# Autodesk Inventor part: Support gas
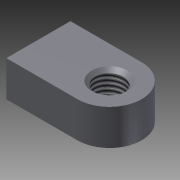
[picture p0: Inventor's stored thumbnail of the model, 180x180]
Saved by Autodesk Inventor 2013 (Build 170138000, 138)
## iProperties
Shininess: 64.0
Length Units: 11269
Angle Units: 11279
Time Units: 11290
Mass Units: 11283
Length Display Precision: 3
Angle Display Precision: 2
Compacted: True
Part Number: Support gas
Document SubType Name: Modeling
Created: 2005-02
Material: Steel, Mild
Designer: =<Author>
Manufacturer: Standard
Standards Organization: Custom
Description: Support
Density: 7.86 g/cm^3
Mass: 34.1318 g
Surface Area: 19.6117 cm^2
Volume: 4.34247 cm^3
Density: 0.0
Volumn: 0.0
Area: 0.0
PropertySet Name: Model Information
Control State: 0
Master: False
Checked Out: False
Checked Out Date: 2008-10-15
Last Check In Date: 2008-10-15
Author: PVitaliy
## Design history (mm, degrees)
sketch "Эскиз1"
  geometry: L1 (0.047, 0)-(20.047, 0); L2 (20.047, 18)-(0.047, 18); L3 (0.047, 18)-(0.047, 0); C1 r 4 at (20.047, 9); A1 r 9 centre (20.047, 9) between (20.047, 0) and (20.047, 18)
  constraints: 6 end point, 2 centre point, 2 point on circle, 2 tangent, 1 coincident, 1 horizontal, 1 parallel, 1 perpendicular, 1 other
  dimensions: "d0" = 8 diameter of C1; "d1" = 18 distance of L2.end L1.start; "d2" = 20 distance from line of A1.centre L3
extrude "Выдавливание1" new body sketch "Эскиз1" distance "d3" = 10; taper "d4" = 0 deg
chamfer "Фаска1" distance "d5" = 1; stored, may be unused: second distance "d6" = 2, angle "d9" = 45 deg
feature "Резьба1" dims "d7" = 10, "d8" = 0
body "Solid1"
